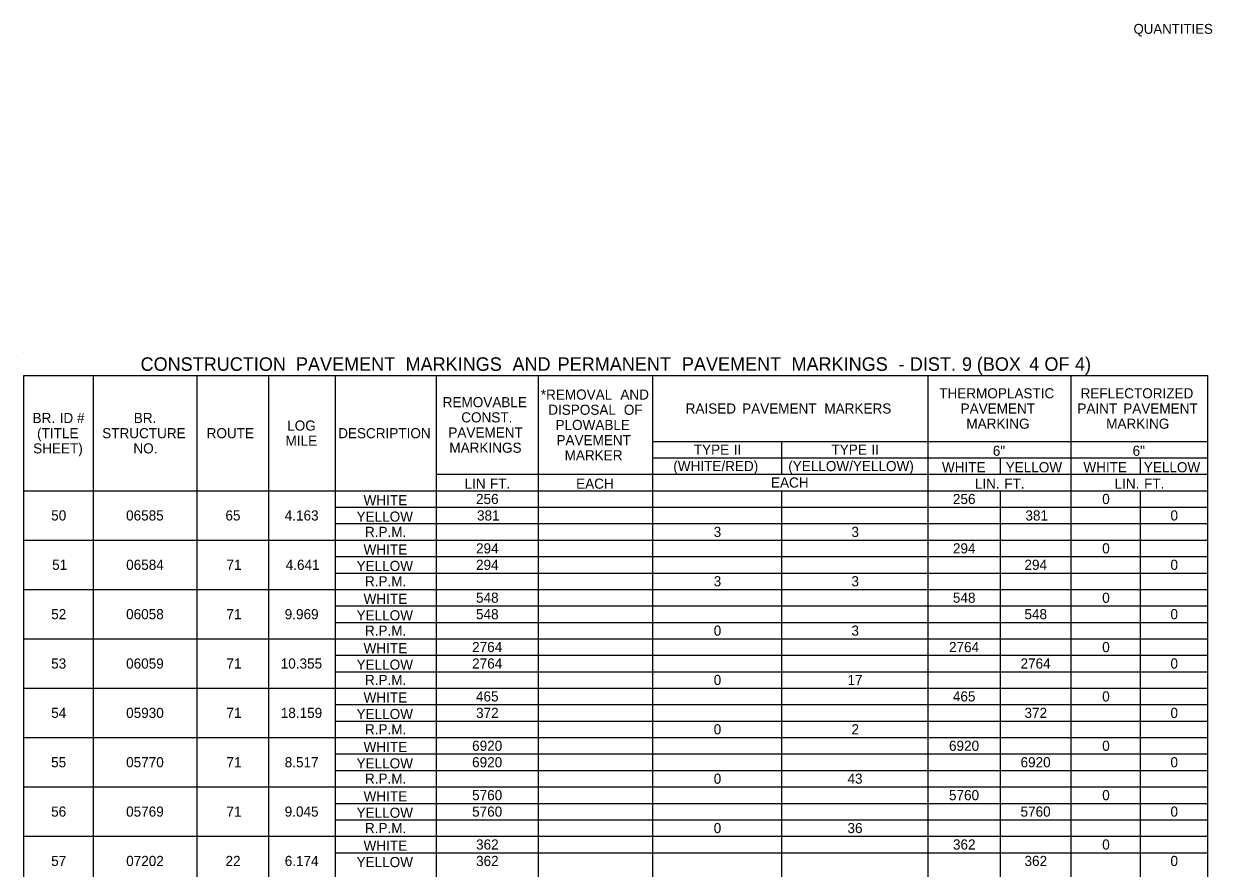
# Model space of a CAD drawing. Extents: x 544420 to 1930787, y -1947044 to 596640.
# Drawn here: x 550705 to 551410, y -1946543 to -1946043 of the extents above; entities that cross this region are included whole.
import ezdxf

# ---------------------------------------------------------------- set-up
doc = ezdxf.new("R2010")
doc.units = 0
doc.layers.add('Default', color=7, linetype='Continuous')
doc.layers.add('R_Border', color=7, linetype='Continuous')

msp = doc.modelspace()

# ---------------------------------------------------------------- linework, layer by layer
at = {"layer": 'Default'}
for p, q in [((550705.2, -1946237.62), (550705.2, -1946237.62)), ((550705.2, -1946251.27), (551407.2, -1946251.27)), ((550705.2, -1946251.27), (551010.38, -1946251.27)), ((550705.2, -1946779.72), (550705.2, -1946251.27)), ((550746.64, -1946769), (550746.64, -1946251.27)), ((550808.07, -1946769), (550808.07, -1946251.27)), ((550850.48, -1946769), (550850.48, -1946251.27)), ((550889.97, -1946769), (550889.97, -1946251.27)), ((550949.93, -1946779.72), (550949.93, -1946251.27)), ((551010.38, -1946779.72), (551010.38, -1946251.27)), ((551078.14, -1946779.72), (551078.14, -1946251.27)), ((551241.45, -1946779.72), (551241.45, -1946251.27)), ((551326.28, -1946319.52), (551326.28, -1946251.27)), ((551326.28, -1946779.72), (551326.28, -1946251.27)), ((551407.2, -1946779.72), (551407.2, -1946251.27)), ((551078.14, -1946290.27), (551407.2, -1946290.27)), ((551154.68, -1946309.77), (551154.68, -1946290.27)), ((551078.14, -1946300.02), (551407.2, -1946300.02)), ((551284.35, -1946309.77), (551284.35, -1946300.02)), ((551367.23, -1946309.77), (551367.23, -1946300.02)), ((550949.93, -1946309.77), (551407.2, -1946309.77)), ((550949.93, -1946319.52), (550949.93, -1946309.77)), ((551010.38, -1946319.52), (551010.38, -1946309.77)), ((551078.14, -1946319.52), (551078.14, -1946309.77)), ((550705.2, -1946319.52), (550889.97, -1946319.52)), ((550705.2, -1946319.52), (550850.48, -1946319.52)), ((550850.48, -1946319.52), (551407.2, -1946319.52)), ((551154.68, -1946779.72), (551154.68, -1946319.52)), ((551241.45, -1946319.52), (551326.28, -1946319.52)), ((551284.35, -1946779.72), (551284.35, -1946319.52)), ((551326.28, -1946319.52), (551407.2, -1946319.52)), ((551367.23, -1946779.72), (551367.23, -1946319.52)), ((550889.97, -1946329.27), (551407.2, -1946329.27)), ((550889.97, -1946339.02), (551407.2, -1946339.02)), ((550705.2, -1946348.77), (551407.2, -1946348.77)), ((550889.97, -1946358.52), (551407.2, -1946358.52)), ((550889.97, -1946368.27), (551407.2, -1946368.27)), ((550705.2, -1946378.02), (551407.2, -1946378.02)), ((550889.97, -1946387.77), (551407.2, -1946387.77)), ((550889.97, -1946397.52), (551407.2, -1946397.52)), ((550705.2, -1946407.27), (551407.2, -1946407.27)), ((550889.97, -1946417.02), (551407.2, -1946417.02)), ((550889.97, -1946426.77), (551407.2, -1946426.77)), ((550705.2, -1946436.52), (551407.2, -1946436.52)), ((550889.97, -1946446.27), (551407.2, -1946446.27)), ((550889.97, -1946456.02), (551407.2, -1946456.02)), ((550705.2, -1946465.77), (551407.2, -1946465.77)), ((550889.97, -1946475.52), (551407.2, -1946475.52)), ((550889.97, -1946485.27), (551407.2, -1946485.27)), ((550705.2, -1946495.02), (551407.2, -1946495.02)), ((550889.97, -1946504.77), (551407.2, -1946504.77)), ((550889.97, -1946514.52), (551407.2, -1946514.52)), ((550705.2, -1946524.27), (551407.2, -1946524.27)), ((550889.97, -1946534.02), (551407.2, -1946534.02))]:
    msp.add_line(p, q, dxfattribs=at)

# ---------------------------------------------------------------- texts
for s, height, p in [('CONSTRUCTION', 8, (550774.45, -1946248.45)), (' PAVEMENT', 8, (550863.6, -1946248.45)), (' MARKINGS', 8, (550928.59, -1946248.45)), (' AND', 8, (550992, -1946248.45)), (' PERMANENT', 8, (551018.77, -1946248.45)), (' PAVEMENT', 8, (551092.45, -1946248.45)), (' MARKINGS', 8, (551157.43, -1946248.45)), (' -', 8, (551220.85, -1946248.45)), (' DIST.', 8, (551227.59, -1946248.45)), (' 9', 8, (551258.5, -1946248.45)), (' (BOX', 8, (551267.29, -1946248.45)), (' 4', 8, (551298.33, -1946248.45)), (' OF', 8, (551307.39, -1946248.45)), (' 4)', 8, (551325.5, -1946248.45)), ('*REMOVAL', 6, (551011.76, -1946265.52)), (' AND', 6, (551056.69, -1946265.52)), ('THERMOPLASTIC', 6, (551247.98, -1946264.77)), ('REFLECTORIZED', 6, (551331.78, -1946264.77)), ('REMOVABLE', 6, (550953.58, -1946270.02)), ('RAISED', 6, (551097.64, -1946273.77)), (' PAVEMENT', 6, (551128.9, -1946273.77)), (' MARKERS', 6, (551177.65, -1946273.77)), ('PAVEMENT', 6, (551260.66, -1946273.77)), ('PAINT', 6, (551329.88, -1946273.77)), (' PAVEMENT', 6, (551354.86, -1946273.77)), ('BR.', 6, (550710.4, -1946279.4)), (' ID', 6, (550724.26, -1946279.4)), (' #', 6, (550734.55, -1946279.4)), ('BR.', 6, (550770.42, -1946279.4)), ('CONST.', 6, (550964.6, -1946279.02)), ('DISPOSAL', 6, (551016.16, -1946274.52)), (' OF', 6, (551058.77, -1946274.52)), ('(TITLE', 6, (550713.09, -1946288.4)), ('LOG', 6, (550861.39, -1946283.9)), ('PAVEMENT', 6, (550956.95, -1946288.02)), ('PLOWABLE', 6, (551020.48, -1946283.52)), ('MARKING', 6, (551264.09, -1946282.77)), ('MARKING', 6, (551346.97, -1946282.77)), ('STRUCTURE', 6, (550751.71, -1946288.4)), ('ROUTE', 6, (550813.64, -1946288.4)), ('MILE', 6, (550860.42, -1946292.9)), ('DESCRIPTION', 6, (550891.63, -1946288.4)), ('PAVEMENT', 6, (551021.05, -1946292.52)), ('SHEET)', 6, (550710.77, -1946297.4)), ('NO.', 6, (550770.19, -1946297.4)), ('MARKINGS', 6, (550957.54, -1946297.02)), ('MARKER', 6, (551025.88, -1946301.52)), ('TYPE', 6, (551102.45, -1946298.15)), (' II', 6, (551123.93, -1946298.15)), ('TYPE', 6, (551184.1, -1946298.15)), (' II', 6, (551205.59, -1946298.15)), ('6"', 6, (551279.76, -1946298.82)), ('6"', 6, (551362.63, -1946298.82)), ('(WHITE/RED)', 6, (551090.32, -1946307.9)), ('(YELLOW/YELLOW)', 6, (551158.47, -1946307.9)), ('WHITE', 6, (551249.61, -1946308.57)), ('YELLOW', 6, (551287.39, -1946308.57)), ('WHITE', 6, (551333.46, -1946308.57)), ('YELLOW', 6, (551369.29, -1946308.57)), ('LIN', 6, (550966.58, -1946318.32)), (' FT.', 6, (550979.41, -1946318.32)), ('EACH', 6, (551032.7, -1946318.32)), ('EACH', 6, (551148.24, -1946317.65)), ('LIN.', 6, (551269.08, -1946318.32)), (' FT.', 6, (551284.33, -1946318.32)), ('LIN.', 6, (551351.95, -1946318.32)), (' FT.', 6, (551367.21, -1946318.32)), ('WHITE', 6, (550906.67, -1946328.07)), ('256', 6, (550973.35, -1946327.4)), ('256', 6, (551256.1, -1946327.4)), ('0', 6, (551344.62, -1946327.4)), ('50', 6, (550721.46, -1946337.15)), ('06585', 6, (550765.87, -1946337.15)), ('65', 6, (550824.78, -1946337.15)), ('4.163', 6, (550859.93, -1946337.15)), ('381', 6, (550973.93, -1946337.15)), ('381', 6, (551299.1, -1946337.15)), ('0', 6, (551385.09, -1946337.15)), ('YELLOW', 6, (550902.53, -1946337.82)), ('R.P.M.', 6, (550907.51, -1946346.9)), ('3', 6, (551114.27, -1946346.9)), ('3', 6, (551195.93, -1946346.9)), ('WHITE', 6, (550906.67, -1946357.32)), ('294', 6, (550973.37, -1946356.65)), ('294', 6, (551256.12, -1946356.65)), ('0', 6, (551344.62, -1946356.65)), ('51', 6, (550722.03, -1946366.4)), ('06584', 6, (550765.91, -1946366.4)), ('71', 6, (550825.38, -1946366.4)), ('4.641', 6, (550860.51, -1946366.4)), ('YELLOW', 6, (550902.53, -1946367.07)), ('294', 6, (550973.37, -1946366.4)), ('294', 6, (551298.53, -1946366.4)), ('0', 6, (551385.09, -1946366.4)), ('R.P.M.', 6, (550907.51, -1946376.15)), ('3', 6, (551114.27, -1946376.15)), ('3', 6, (551195.93, -1946376.15)), ('WHITE', 6, (550906.67, -1946386.57)), ('548', 6, (550973.35, -1946385.9)), ('548', 6, (551256.1, -1946385.9)), ('0', 6, (551344.62, -1946385.9)), ('52', 6, (550721.48, -1946395.65)), ('06058', 6, (550765.89, -1946395.65)), ('71', 6, (550825.38, -1946395.65)), ('9.969', 6, (550859.92, -1946395.65)), ('YELLOW', 6, (550902.53, -1946396.32)), ('548', 6, (550973.35, -1946395.65)), ('548', 6, (551298.51, -1946395.65)), ('0', 6, (551385.09, -1946395.65)), ('R.P.M.', 6, (550907.51, -1946405.4)), ('0', 6, (551114.28, -1946405.4)), ('3', 6, (551195.93, -1946405.4)), ('WHITE', 6, (550906.67, -1946415.82)), ('2764', 6, (550971.04, -1946415.15)), ('2764', 6, (551253.79, -1946415.15)), ('0', 6, (551344.62, -1946415.15)), ('53', 6, (550721.45, -1946424.9)), ('06059', 6, (550765.89, -1946424.9)), ('71', 6, (550825.38, -1946424.9)), ('10.355', 6, (550857.57, -1946424.9)), ('YELLOW', 6, (550902.53, -1946425.57)), ('2764', 6, (550971.04, -1946424.9)), ('2764', 6, (551296.2, -1946424.9)), ('0', 6, (551385.09, -1946424.9)), ('R.P.M.', 6, (550907.51, -1946434.65)), ('0', 6, (551114.28, -1946434.65)), ('17', 6, (551193.6, -1946434.65)), ('WHITE', 6, (550906.67, -1946445.07)), ('465', 6, (550973.33, -1946444.4)), ('465', 6, (551256.08, -1946444.4)), ('0', 6, (551344.62, -1946444.4)), ('54', 6, (550721.47, -1946454.15)), ('05930', 6, (550765.9, -1946454.15)), ('71', 6, (550825.38, -1946454.15)), ('18.159', 6, (550857.59, -1946454.15)), ('YELLOW', 6, (550902.53, -1946454.82)), ('372', 6, (550973.38, -1946454.15)), ('372', 6, (551298.55, -1946454.15)), ('0', 6, (551385.09, -1946454.15)), ('R.P.M.', 6, (550907.51, -1946463.9)), ('0', 6, (551114.28, -1946463.9)), ('2', 6, (551195.96, -1946463.9)), ('WHITE', 6, (550906.67, -1946474.32)), ('6920', 6, (550971.03, -1946473.65)), ('6920', 6, (551253.78, -1946473.65)), ('0', 6, (551344.62, -1946473.65)), ('55', 6, (550721.43, -1946483.4)), ('05770', 6, (550765.9, -1946483.4)), ('71', 6, (550825.38, -1946483.4)), ('8.517', 6, (550859.93, -1946483.4)), ('YELLOW', 6, (550902.53, -1946484.07)), ('6920', 6, (550971.03, -1946483.4)), ('6920', 6, (551296.2, -1946483.4)), ('0', 6, (551385.09, -1946483.4)), ('R.P.M.', 6, (550907.51, -1946493.15)), ('0', 6, (551114.28, -1946493.15)), ('43', 6, (551193.6, -1946493.15)), ('WHITE', 6, (550906.67, -1946503.57)), ('5760', 6, (550971.03, -1946502.9)), ('5760', 6, (551253.78, -1946502.9)), ('0', 6, (551344.62, -1946502.9)), ('56', 6, (550721.45, -1946512.65)), ('05769', 6, (550765.89, -1946512.65)), ('71', 6, (550825.38, -1946512.65)), ('9.045', 6, (550859.9, -1946512.65)), ('YELLOW', 6, (550902.53, -1946513.32)), ('5760', 6, (550971.03, -1946512.65)), ('5760', 6, (551296.2, -1946512.65)), ('0', 6, (551385.09, -1946512.65)), ('R.P.M.', 6, (550907.51, -1946522.4)), ('0', 6, (551114.28, -1946522.4)), ('36', 6, (551193.6, -1946522.4)), ('WHITE', 6, (550906.67, -1946532.82)), ('362', 6, (550973.38, -1946532.15)), ('362', 6, (551256.13, -1946532.15)), ('0', 6, (551344.62, -1946532.15)), ('57', 6, (550721.45, -1946541.9)), ('07202', 6, (550765.92, -1946541.9)), ('22', 6, (550824.83, -1946541.9)), ('6.174', 6, (550859.94, -1946541.9)), ('YELLOW', 6, (550902.53, -1946542.57)), ('362', 6, (550973.38, -1946541.9)), ('362', 6, (551298.55, -1946541.9)), ('0', 6, (551385.09, -1946541.9))]:
    msp.add_text(s, height=height, dxfattribs=at).set_placement(p)
at = {"layer": 'R_Border'}
msp.add_text('QUANTITIES', height=5.862, rotation=360, dxfattribs=at).set_placement((551363.17, -1946048.73))

doc.saveas('drawing.dxf')
